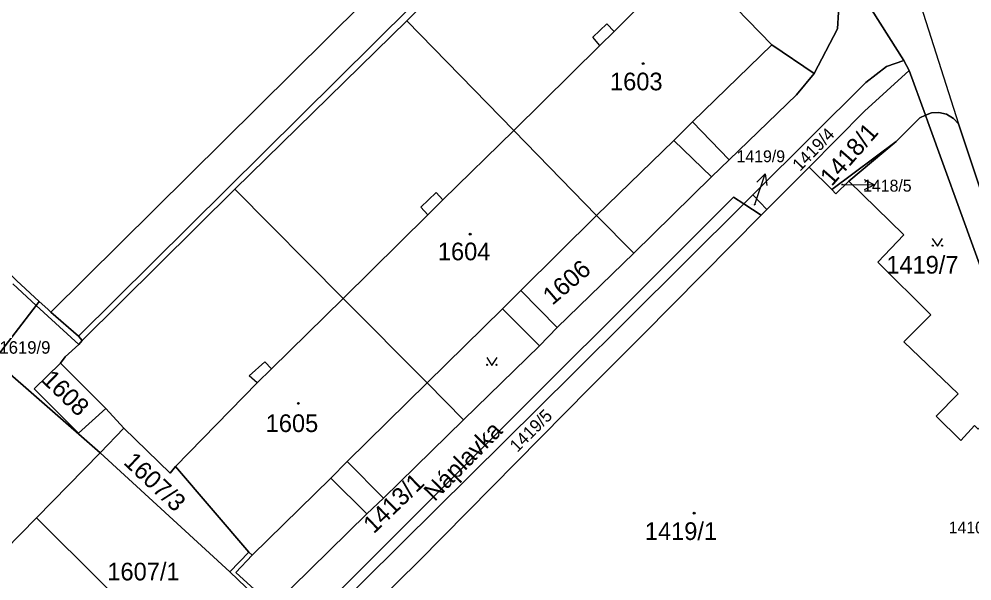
# Model space of a CAD drawing. Extents: x -598934 to -598196, y -1162208 to -1161502.
# Drawn here: x -598777.9 to -598686.2, y -1161695.5 to -1161641.4 of the extents above; entities that cross this region are included whole.
import ezdxf

# ---------------------------------------------------------------- set-up
doc = ezdxf.new("R2010")
doc.units = 0
for name, color, linetype in [('KN_CAR_KR', 7, 'Continuous'), ('KN_KULTURY', 7, 'Continuous'), ('KN_PARC_CIS_POM', 7, 'Continuous'), ('KN_PARC_CIS_POZ', 7, 'Continuous'), ('KN_PARC_CIS_STAV', 7, 'Continuous'), ('KN_PARC_PLOCHA', 7, 'Continuous'), ('KN_ULICE', 7, 'Continuous'), ('PARC_C_SIPKA', 7, 'Continuous'), ('parcely_l', 7, 'Continuous')]:
    doc.layers.add(name, color=color, linetype=linetype)

msp = doc.modelspace()

# ---------------------------------------------------------------- linework, layer by layer
at = {"layer": 'KN_CAR_KR'}
for points in [[(-598774.83, -1161669.62), (-598728.27, -1161623.48)], [(-598725.84, -1161626), (-598772.17, -1161671.95)], [(-598693.51, -1161632.59), (-598687.48, -1161651.51)], [(-598720.61, -1161642.61), (-598715.07, -1161637.08)], [(-598722.68, -1161643.17), (-598721.34, -1161641.88)], [(-598721.99, -1161643.97), (-598720.61, -1161642.61)], [(-598721.34, -1161641.88), (-598720.61, -1161642.61)], [(-598721.99, -1161643.97), (-598722.68, -1161643.17)], [(-598730.27, -1161652.14), (-598721.99, -1161643.97)], [(-598709.54, -1161654.96), (-598713.09, -1161651.31)], [(-598737.1, -1161658.82), (-598730.27, -1161652.14)], [(-598714.87, -1161653.1), (-598711.24, -1161656.61)], [(-598739.24, -1161659.54), (-598737.75, -1161658.13)], [(-598737.75, -1161658.13), (-598737.1, -1161658.82)], [(-598738.57, -1161660.27), (-598737.1, -1161658.82)], [(-598738.57, -1161660.27), (-598739.24, -1161659.54)], [(-598746.71, -1161668.31), (-598738.57, -1161660.27)], [(-598722.32, -1161660.32), (-598718.72, -1161663.97)], [(-598776.24, -1161668.98), (-598778.49, -1161666.91)], [(-598753.59, -1161675.08), (-598746.71, -1161668.31)], [(-598726.1, -1161671.1), (-598729.62, -1161667.55)], [(-598772.15, -1161672.73), (-598776.24, -1161668.98)], [(-598731.37, -1161669.32), (-598727.82, -1161672.87)], [(-598755.74, -1161675.77), (-598754.23, -1161674.42)], [(-598754.23, -1161674.42), (-598753.59, -1161675.08)], [(-598754.99, -1161676.43), (-598753.59, -1161675.08)], [(-598762.84, -1161684.49), (-598754.99, -1161676.43)], [(-598754.99, -1161676.43), (-598755.74, -1161675.77)], [(-598738.62, -1161676.44), (-598735.13, -1161679.98)], [(-598742.83, -1161687.52), (-598746.32, -1161683.99)], [(-598747.9, -1161685.6), (-598744.42, -1161689.04)], [(-598755.77, -1161692.74), (-598757.62, -1161694.64)]]:
    msp.add_lwpolyline(points, dxfattribs=at)
at = {"layer": 'KN_KULTURY'}
for points in [[(-598690.012, -1161662.532), (-598689.512, -1161663.282), (-598689.012, -1161662.532)], [(-598732.892, -1161674.002), (-598732.392, -1161674.752), (-598731.892, -1161674.002)]]:
    msp.add_lwpolyline(points, dxfattribs=at)
for centre, radius in [((-598717.84, -1161645.71), 0.09), ((-598717.84, -1161645.71), 0.0398), ((-598734.48, -1161662.12), 0.09), ((-598734.48, -1161662.12), 0.0398), ((-598689.962, -1161663.231), 0.05), ((-598689.063, -1161663.231), 0.05), ((-598732.842, -1161674.701), 0.05), ((-598731.943, -1161674.701), 0.05), ((-598751.02, -1161678.41), 0.09), ((-598751.02, -1161678.41), 0.0398), ((-598712.93, -1161688.97), 0.09), ((-598712.93, -1161688.97), 0.0398)]:
    msp.add_circle(centre, radius, dxfattribs=at)
at = {"layer": 'KN_PARC_PLOCHA'}
for points in [[(-598725.32, -1161626.54), (-598740.59, -1161641.59), (-598757.12, -1161657.78), (-598771.81, -1161672.37), (-598772.17, -1161671.95), (-598774.83, -1161669.62), (-598775.12, -1161669.35), (-598775.95, -1161668.6), (-598778.16, -1161666.6), (-598801.19, -1161643.07), (-598802.29, -1161642.59), (-598825.81, -1161634.98)], [(-598753.47, -1161697.94), (-598744.42, -1161689.04), (-598742.83, -1161687.52), (-598735.13, -1161679.98), (-598727.82, -1161672.87), (-598726.1, -1161671.1), (-598718.72, -1161663.97), (-598711.24, -1161656.61), (-598709.54, -1161654.96), (-598703.09, -1161648.71), (-598701.38, -1161646.66), (-598699.14, -1161642.35), (-598698.75, -1161635.93), (-598692.75, -1161645.4), (-598694.4, -1161645.98), (-598696.4, -1161647.52), (-598707.07, -1161658.14), (-598707.29, -1161658.35), (-598708.15, -1161659.2), (-598709.13, -1161658.56), (-598766.4, -1161715.78)], [(-598698.75, -1161635.93), (-598699.14, -1161642.35), (-598701.38, -1161646.66), (-598705.45, -1161643.89), (-598713.46, -1161635.61)], [(-598678.03, -1161679.94), (-598687.48, -1161651.51), (-598687.98, -1161650.98), (-598688.63, -1161650.59), (-598689.38, -1161650.41), (-598690.08, -1161650.46), (-598690.66, -1161650.66), (-598692.23, -1161646.38), (-598692.75, -1161645.4), (-598698.75, -1161635.93)], [(-598747.18, -1161701.25), (-598739.47, -1161693.64), (-598722.96, -1161676.93), (-598717.87, -1161671.81), (-598706.47, -1161660.3), (-598705.92, -1161659.75), (-598701.86, -1161655.67), (-598699.68, -1161657.84), (-598699.29, -1161658.23), (-598698.04, -1161657.01), (-598692.73, -1161662.19), (-598695.26, -1161664.81), (-598690.15, -1161669.88), (-598692.75, -1161672.48), (-598687.53, -1161677.48), (-598689.63, -1161679.64), (-598687.25, -1161681.97), (-598685.95, -1161680.54)], [(-598778.16, -1161666.6), (-598775.95, -1161668.6), (-598776.24, -1161668.98), (-598780.33, -1161674.26), (-598770.1, -1161683.17), (-598776.21, -1161689.42), (-598779.27, -1161692.54)], [(-598779.27, -1161692.54), (-598776.21, -1161689.42), (-598763.53, -1161702.08), (-598764.68, -1161703.18), (-598764.95, -1161703.44), (-598766.85, -1161705.26), (-598773.96, -1161697.83), (-598778.79, -1161702.55)]]:
    msp.add_lwpolyline(points, dxfattribs=at)
for points in [[(-598705.45, -1161643.89), (-598713.09, -1161651.31), (-598714.87, -1161653.1), (-598722.32, -1161660.32), (-598730.27, -1161652.14), (-598740.59, -1161641.59), (-598725.32, -1161626.54), (-598725.09, -1161626.29), (-598715.07, -1161637.08), (-598713.46, -1161635.61)], [(-598722.32, -1161660.32), (-598729.62, -1161667.55), (-598731.37, -1161669.32), (-598738.62, -1161676.44), (-598746.71, -1161668.31), (-598757.12, -1161657.78), (-598740.59, -1161641.59), (-598730.27, -1161652.14)], [(-598701.38, -1161646.66), (-598703.09, -1161648.71), (-598709.54, -1161654.96), (-598711.24, -1161656.61), (-598718.72, -1161663.97), (-598726.1, -1161671.1), (-598727.82, -1161672.87), (-598735.13, -1161679.98), (-598742.83, -1161687.52), (-598744.42, -1161689.04), (-598753.47, -1161697.94), (-598757.02, -1161694.7), (-598755.47, -1161693.03), (-598747.9, -1161685.6), (-598746.32, -1161683.99), (-598738.62, -1161676.44), (-598731.37, -1161669.32), (-598729.62, -1161667.55), (-598722.32, -1161660.32), (-598714.87, -1161653.1), (-598713.09, -1161651.31), (-598705.45, -1161643.89)], [(-598692.23, -1161646.38), (-598696.53, -1161650.3), (-598701.86, -1161655.67), (-598705.92, -1161659.75), (-598707.29, -1161658.35), (-598707.07, -1161658.14), (-598696.4, -1161647.52), (-598694.4, -1161645.98), (-598692.75, -1161645.4)], [(-598690.66, -1161650.66), (-598691.2, -1161650.93), (-598693.48, -1161653.2), (-598699.68, -1161657.84), (-598701.86, -1161655.67), (-598696.53, -1161650.3), (-598692.23, -1161646.38)], [(-598681.27, -1161676.6), (-598685.58, -1161680.89), (-598685.95, -1161680.54), (-598687.25, -1161681.97), (-598689.63, -1161679.64), (-598687.53, -1161677.48), (-598692.75, -1161672.48), (-598690.15, -1161669.88), (-598695.26, -1161664.81), (-598692.73, -1161662.19), (-598698.04, -1161657.01), (-598693.48, -1161653.2), (-598691.2, -1161650.93), (-598690.66, -1161650.66), (-598690.42, -1161651.33)], [(-598673.72, -1161694.38), (-598674.87, -1161692.27), (-598676.62, -1161688.4), (-598678.51, -1161684.23), (-598681.27, -1161676.6), (-598690.42, -1161651.33), (-598690.66, -1161650.66), (-598690.08, -1161650.46), (-598689.38, -1161650.41), (-598688.63, -1161650.59), (-598687.98, -1161650.98), (-598687.48, -1161651.51), (-598678.03, -1161679.94), (-598675.38, -1161685.5), (-598671.58, -1161692.3)], [(-598698.04, -1161657.01), (-598699.29, -1161658.23), (-598699.68, -1161657.84), (-598693.48, -1161653.2)], [(-598738.62, -1161676.44), (-598746.32, -1161683.99), (-598747.9, -1161685.6), (-598755.47, -1161693.03), (-598755.77, -1161692.74), (-598762.84, -1161684.49), (-598763.36, -1161685.12), (-598767.8, -1161680.81), (-598769.56, -1161678.91), (-598773.92, -1161674.54), (-598773.46, -1161673.93), (-598772.15, -1161672.73), (-598771.81, -1161672.37), (-598757.12, -1161657.78), (-598746.71, -1161668.31)], [(-598708.15, -1161659.2), (-598719.3, -1161670.3), (-598724.54, -1161675.5), (-598741.08, -1161691.91), (-598760.1, -1161710.77), (-598762.21, -1161714.59), (-598763.52, -1161718.51), (-598766.4, -1161715.78), (-598709.13, -1161658.56)], [(-598705.92, -1161659.75), (-598706.47, -1161660.3), (-598708.15, -1161659.2), (-598707.29, -1161658.35)], [(-598706.47, -1161660.3), (-598717.87, -1161671.81), (-598722.96, -1161676.93), (-598739.47, -1161693.64), (-598747.18, -1161701.25), (-598752.32, -1161706.54), (-598754.19, -1161708.41), (-598755.12, -1161711.72), (-598756.4, -1161710.56), (-598757.96, -1161712.41), (-598759.68, -1161714.2), (-598758.75, -1161715.13), (-598759.23, -1161715.94), (-598757.75, -1161717.39), (-598763.52, -1161718.51), (-598762.21, -1161714.59), (-598760.1, -1161710.77), (-598741.08, -1161691.91), (-598724.54, -1161675.5), (-598719.3, -1161670.3), (-598708.15, -1161659.2)], [(-598771.81, -1161672.37), (-598772.15, -1161672.73), (-598773.46, -1161673.93), (-598773.92, -1161674.54), (-598776.43, -1161677.01), (-598772.19, -1161681.29), (-598769.56, -1161678.91), (-598767.8, -1161680.81), (-598770.1, -1161683.17), (-598780.33, -1161674.26), (-598776.24, -1161668.98), (-598775.95, -1161668.6), (-598775.12, -1161669.35), (-598774.83, -1161669.62), (-598772.17, -1161671.95)], [(-598769.56, -1161678.91), (-598772.19, -1161681.29), (-598776.43, -1161677.01), (-598773.92, -1161674.54)], [(-598755.47, -1161693.03), (-598757.02, -1161694.7), (-598753.47, -1161697.94), (-598753.8, -1161698.27), (-598757.62, -1161694.64), (-598770.1, -1161683.17), (-598767.8, -1161680.81), (-598763.36, -1161685.12), (-598762.84, -1161684.49), (-598755.77, -1161692.74)], [(-598753.8, -1161698.27), (-598763.35, -1161708.9), (-598763.51, -1161708.63), (-598766.85, -1161705.26), (-598764.95, -1161703.44), (-598764.68, -1161703.18), (-598763.53, -1161702.08), (-598776.21, -1161689.42), (-598770.1, -1161683.17), (-598757.62, -1161694.64)]]:
    msp.add_lwpolyline(points, close=True, dxfattribs=at)
at = {"layer": 'PARC_C_SIPKA'}
for points in [[(-598707.11, -1161659.32), (-598707.06, -1161659.17), (-598706.082, -1161656.334)], [(-598706.88, -1161657.116), (-598706.082, -1161656.334), (-598705.935, -1161657.442)], [(-598696.563, -1161656.859), (-598695.57, -1161657.373), (-598696.577, -1161657.859)], [(-598698.76, -1161657.33), (-598698.57, -1161657.33), (-598695.57, -1161657.373)]]:
    msp.add_lwpolyline(points, dxfattribs=at)
at = {"layer": 'parcely_l'}
for points in [[(-598740.59, -1161641.59), (-598725.32, -1161626.54)], [(-598725.32, -1161626.54), (-598725.09, -1161626.29), (-598715.07, -1161637.08), (-598713.46, -1161635.61), (-598705.45, -1161643.89)], [(-598701.38, -1161646.66), (-598699.14, -1161642.35), (-598698.75, -1161635.93)], [(-598692.75, -1161645.4), (-598698.75, -1161635.93)], [(-598757.12, -1161657.78), (-598740.59, -1161641.59)], [(-598722.32, -1161660.32), (-598730.27, -1161652.14), (-598740.59, -1161641.59)], [(-598705.45, -1161643.89), (-598713.09, -1161651.31), (-598714.87, -1161653.1), (-598722.32, -1161660.32)], [(-598705.45, -1161643.89), (-598701.38, -1161646.66)], [(-598707.29, -1161658.35), (-598707.07, -1161658.14), (-598696.4, -1161647.52), (-598694.4, -1161645.98), (-598692.75, -1161645.4)], [(-598692.75, -1161645.4), (-598692.23, -1161646.38)], [(-598701.38, -1161646.66), (-598703.09, -1161648.71), (-598709.54, -1161654.96), (-598711.24, -1161656.61), (-598718.72, -1161663.97), (-598726.1, -1161671.1), (-598727.82, -1161672.87), (-598735.13, -1161679.98), (-598742.83, -1161687.52), (-598744.42, -1161689.04), (-598753.47, -1161697.94)], [(-598692.23, -1161646.38), (-598696.53, -1161650.3), (-598701.86, -1161655.67)], [(-598690.66, -1161650.66), (-598692.23, -1161646.38)], [(-598693.48, -1161653.2), (-598691.2, -1161650.93), (-598690.66, -1161650.66)], [(-598673.72, -1161694.38), (-598671.58, -1161692.3), (-598675.38, -1161685.5), (-598678.03, -1161679.94), (-598687.48, -1161651.51), (-598687.98, -1161650.98), (-598688.63, -1161650.59), (-598689.38, -1161650.41), (-598690.08, -1161650.46), (-598690.66, -1161650.66)], [(-598690.66, -1161650.66), (-598690.42, -1161651.33), (-598681.27, -1161676.6)], [(-598693.48, -1161653.2), (-598699.68, -1161657.84)], [(-598698.04, -1161657.01), (-598693.48, -1161653.2)], [(-598701.86, -1161655.67), (-598705.92, -1161659.75)], [(-598699.68, -1161657.84), (-598701.86, -1161655.67)], [(-598699.68, -1161657.84), (-598699.29, -1161658.23), (-598698.04, -1161657.01)], [(-598685.58, -1161680.89), (-598685.95, -1161680.54), (-598687.25, -1161681.97), (-598689.63, -1161679.64), (-598687.53, -1161677.48), (-598692.75, -1161672.48), (-598690.15, -1161669.88), (-598695.26, -1161664.81), (-598692.73, -1161662.19), (-598698.04, -1161657.01)], [(-598771.81, -1161672.37), (-598757.12, -1161657.78)], [(-598738.62, -1161676.44), (-598746.71, -1161668.31), (-598757.12, -1161657.78)], [(-598766.4, -1161715.78), (-598709.13, -1161658.56), (-598708.15, -1161659.2)], [(-598707.29, -1161658.35), (-598708.15, -1161659.2)], [(-598705.92, -1161659.75), (-598707.29, -1161658.35)], [(-598763.52, -1161718.51), (-598762.21, -1161714.59), (-598760.1, -1161710.77), (-598741.08, -1161691.91), (-598724.54, -1161675.5), (-598719.3, -1161670.3), (-598708.15, -1161659.2)], [(-598708.15, -1161659.2), (-598706.47, -1161660.3)], [(-598706.47, -1161660.3), (-598705.92, -1161659.75)], [(-598706.47, -1161660.3), (-598717.87, -1161671.81), (-598722.96, -1161676.93), (-598739.47, -1161693.64), (-598747.18, -1161701.25), (-598752.32, -1161706.54), (-598754.19, -1161708.41), (-598755.12, -1161711.72), (-598756.4, -1161710.56), (-598757.96, -1161712.41), (-598759.68, -1161714.2), (-598758.75, -1161715.13), (-598759.23, -1161715.94), (-598757.75, -1161717.39)], [(-598722.32, -1161660.32), (-598729.62, -1161667.55), (-598731.37, -1161669.32), (-598738.62, -1161676.44)], [(-598778.16, -1161666.6), (-598775.95, -1161668.6)], [(-598775.95, -1161668.6), (-598776.24, -1161668.98), (-598780.33, -1161674.26), (-598770.1, -1161683.17)], [(-598775.95, -1161668.6), (-598775.12, -1161669.35), (-598774.83, -1161669.62), (-598772.17, -1161671.95), (-598771.81, -1161672.37)], [(-598773.92, -1161674.54), (-598773.46, -1161673.93), (-598772.15, -1161672.73), (-598771.81, -1161672.37)], [(-598769.56, -1161678.91), (-598772.19, -1161681.29), (-598776.43, -1161677.01), (-598773.92, -1161674.54)], [(-598773.92, -1161674.54), (-598769.56, -1161678.91)], [(-598755.47, -1161693.03), (-598747.9, -1161685.6), (-598746.32, -1161683.99), (-598738.62, -1161676.44)], [(-598767.8, -1161680.81), (-598769.56, -1161678.91)], [(-598767.8, -1161680.81), (-598770.1, -1161683.17)], [(-598755.47, -1161693.03), (-598755.77, -1161692.74), (-598762.84, -1161684.49), (-598763.36, -1161685.12), (-598767.8, -1161680.81)], [(-598770.1, -1161683.17), (-598776.21, -1161689.42)], [(-598770.1, -1161683.17), (-598757.62, -1161694.64), (-598753.8, -1161698.27)], [(-598784.94, -1161696.15), (-598780.32, -1161691.61), (-598779.27, -1161692.54), (-598776.21, -1161689.42)], [(-598776.21, -1161689.42), (-598763.53, -1161702.08), (-598764.68, -1161703.18), (-598764.95, -1161703.44), (-598766.85, -1161705.26)], [(-598753.47, -1161697.94), (-598757.02, -1161694.7), (-598755.47, -1161693.03)]]:
    msp.add_lwpolyline(points, dxfattribs=at)

# ---------------------------------------------------------------- texts
at = {"layer": 'KN_PARC_CIS_POM'}
for s, p in [('1418/5', (-598698.893, -1161657.33)), ('1419/9', (-598707.393, -1161659.32))]:
    msp.add_text(s, height=0.1, dxfattribs=at).set_placement(p)
at = {"layer": 'KN_PARC_CIS_POZ'}
for s, height, rotation, p in [('1418/1', 1.7, 48.60101, (-598699.685, -1161657.593)), ('1419/4', 1.2, 45.90034, (-598702.733, -1161656.139)), ('1606', 1.7, 40.49948, (-598726.577, -1161669.03)), ('1608', 1.7, 316.03435, (-598775.813, -1161676.256)), ('1419/5', 1.2, 45, (-598729.951, -1161683.191)), ('1413/1', 1.7, 44.10071, (-598743.768, -1161691.037))]:
    msp.add_text(s, height=height, rotation=rotation, dxfattribs=at).set_placement(p)
for s, height, p in [('1419/9', 1.14, (-598708.84, -1161655.2)), ('1418/5', 1.14, (-598696.66, -1161658.03)), ('1419/7', 1.7, (-598694.437, -1161665.92)), ('1619/9', 1.2, (-598779.79, -1161673.63)), ('1410/11', 1.14, (-598688.425, -1161690.93))]:
    msp.add_text(s, height=height, dxfattribs=at).set_placement(p)
at = {"layer": 'KN_PARC_CIS_STAV'}
for s, p in [('1603', (-598721.022, -1161648.28)), ('1604', (-598737.592, -1161664.64)), ('1605', (-598754.162, -1161681.17)), ('1419/1', (-598717.672, -1161691.56)), ('1607/1', (-598769.402, -1161695.45))]:
    msp.add_text(s, height=1.7, dxfattribs=at).set_placement(p)
msp.add_text('1607/3', height=1.7, rotation=316.79993, dxfattribs=at).set_placement((-598767.932, -1161684.189))
at = {"layer": 'KN_ULICE'}
msp.add_text('Náplavka', height=1.7, rotation=45.44029, dxfattribs=at).set_placement((-598737.907, -1161687.92))

doc.saveas('drawing.dxf')
